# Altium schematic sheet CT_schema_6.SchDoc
size 371 x 333 mm
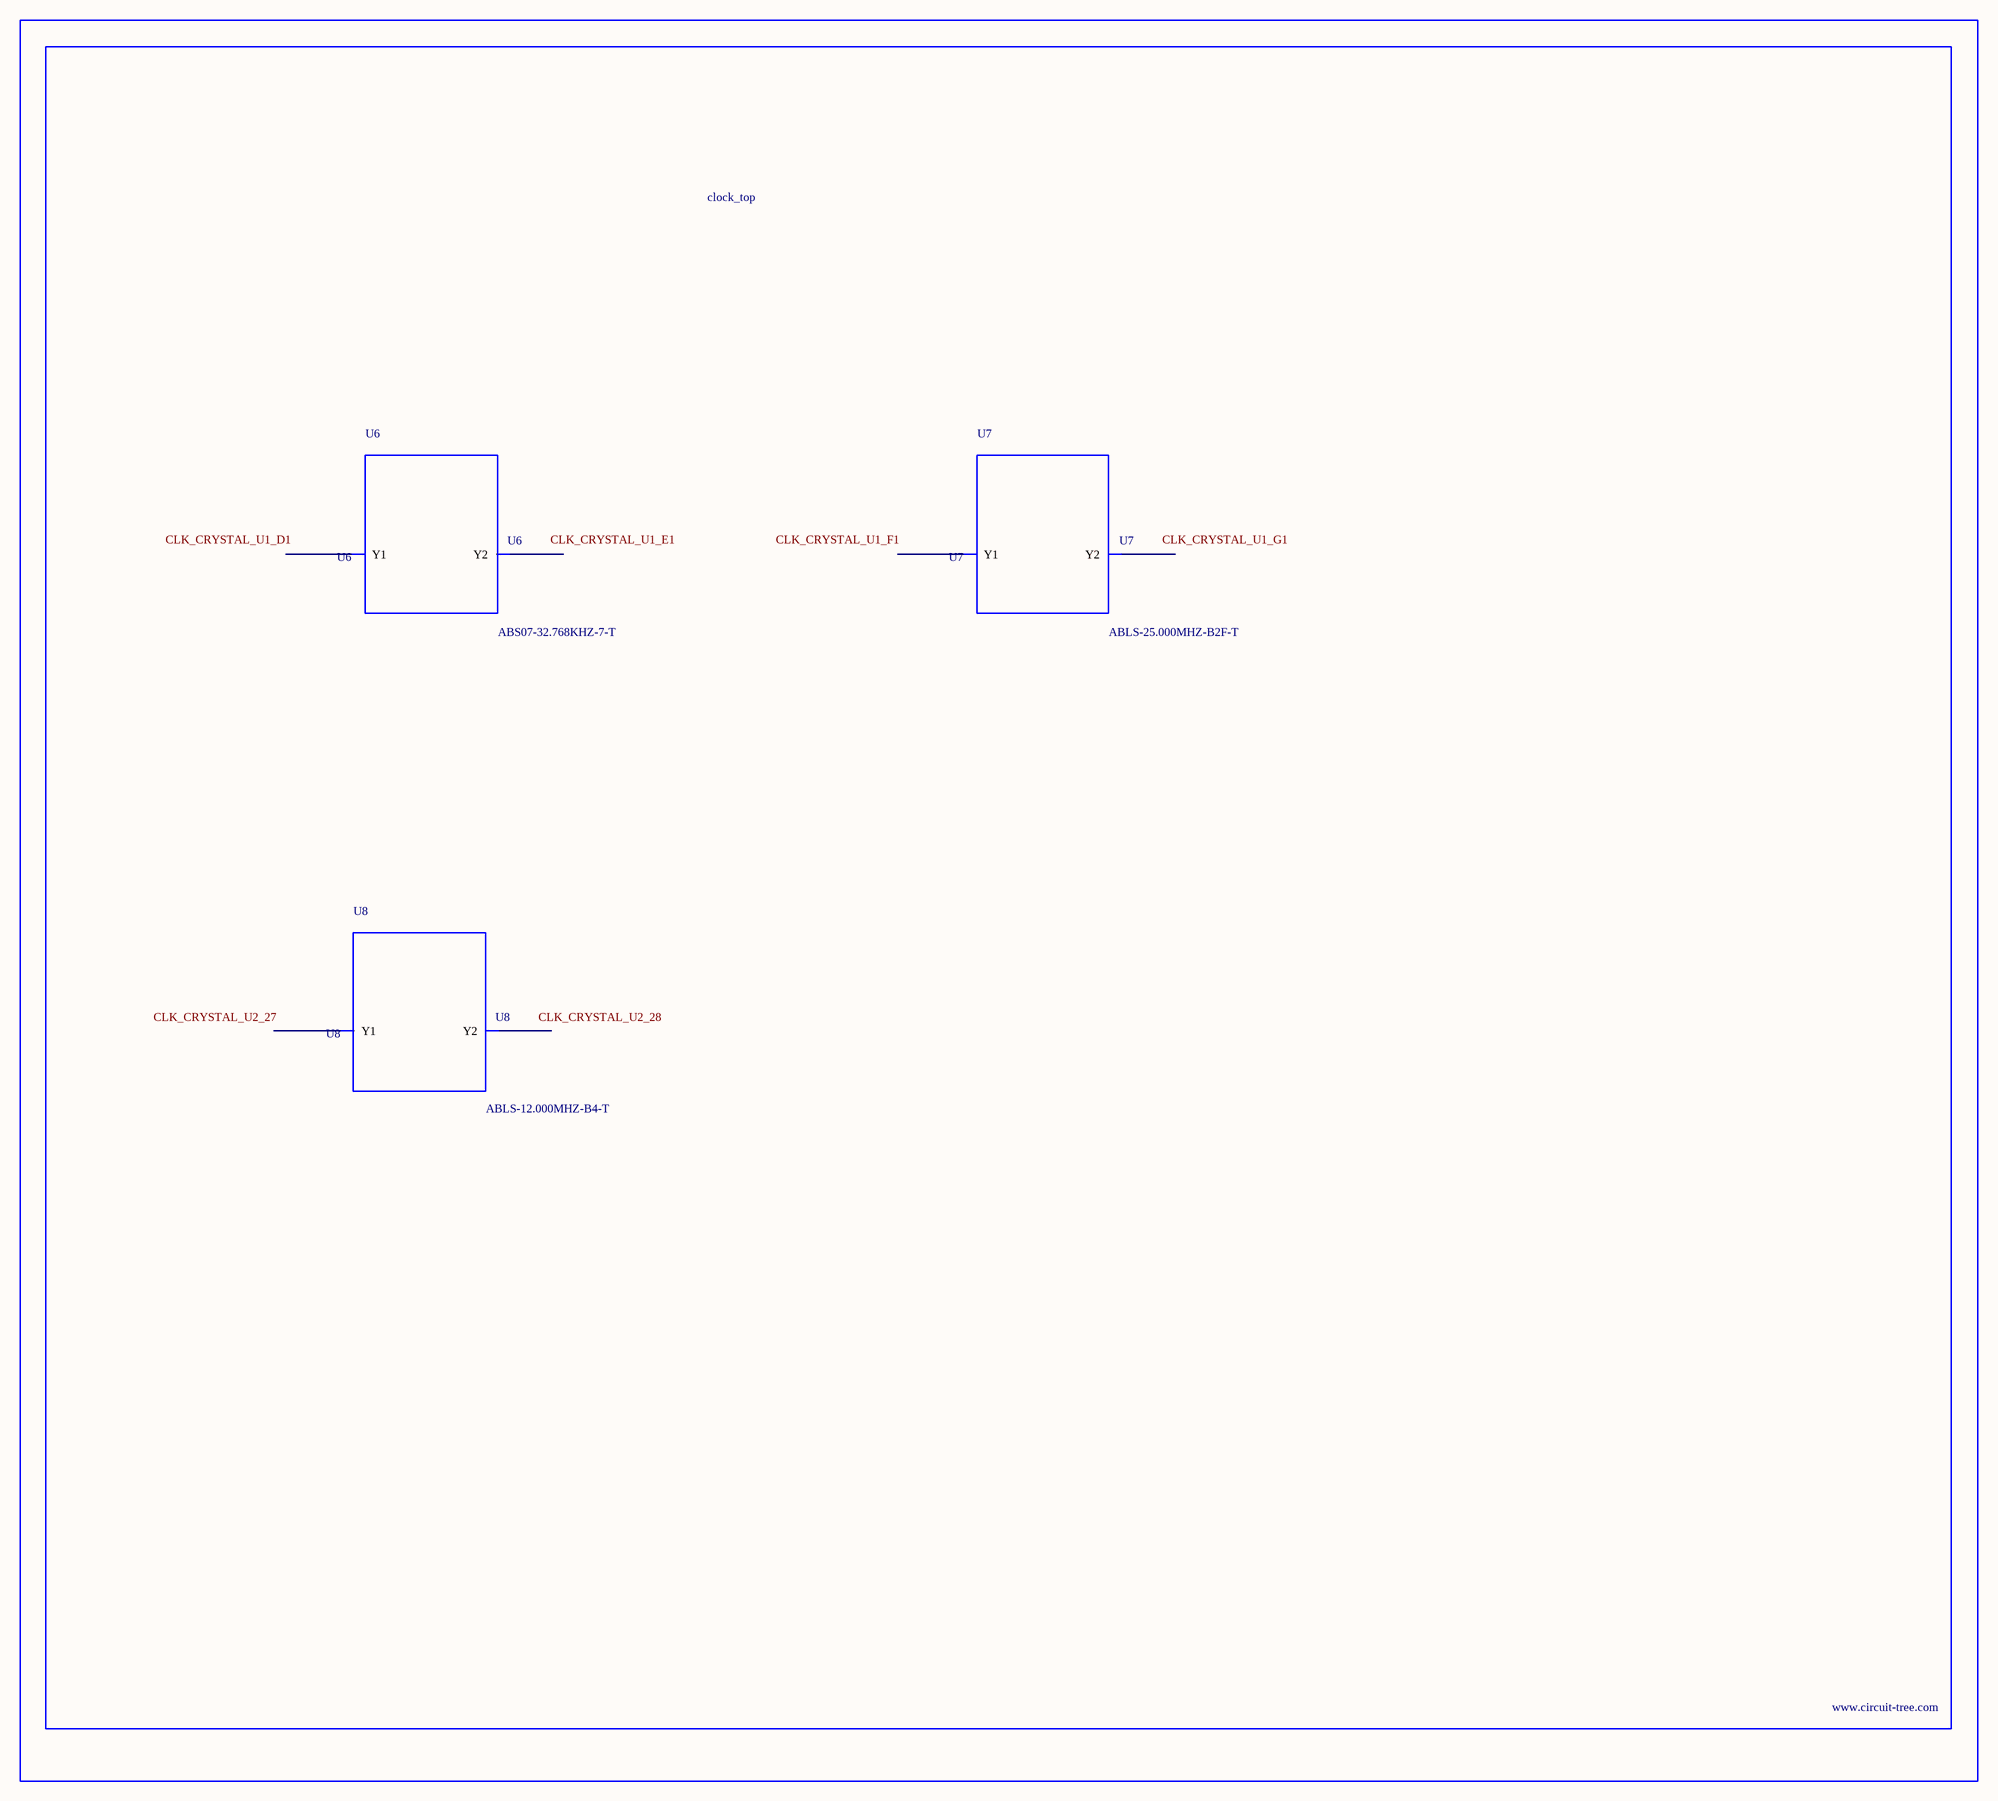
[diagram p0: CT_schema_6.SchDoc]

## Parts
BORDER5  (no value)
U6  ABS07-32.768KHZ-7-T  [ABS07-32.768KHZ-7-T]
U7  ABLS-25.000MHZ-B2F-T  [ABLS-25.000MHZ-B2F-T]
U8  ABLS-12.000MHZ-B4-T  [ABLS-12.000MHZ-B4-T]

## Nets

Not connected (* = marked no-connect by the designer): U6 1(Y1) 2(Y2); U7 1(Y1) 2(Y2); U8 1(Y1) 2(Y2)

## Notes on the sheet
- Labels drawn without touching a wire or pin: CLK_CRYSTAL_U1_D1, CLK_CRYSTAL_U1_E1, CLK_CRYSTAL_U1_F1, CLK_CRYSTAL_U1_G1, CLK_CRYSTAL_U2_27, CLK_CRYSTAL_U2_28

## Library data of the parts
BORDER5 = BORDER_PAGE5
